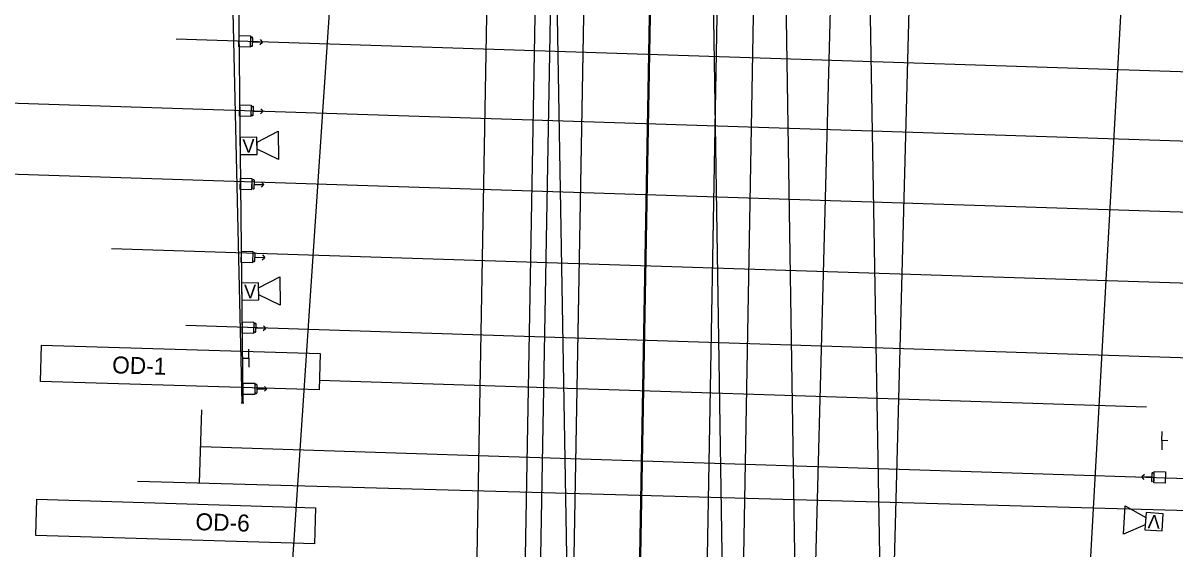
# Model space of a CAD drawing. Extents: x 925524 to 926006, y 853415 to 857998.
# Drawn here: x 925686 to 925876.1, y 853545.3 to 853632 of the extents above; entities that cross this region are included whole.
import ezdxf

# ---------------------------------------------------------------- set-up
doc = ezdxf.new("R2010")
doc.units = 0
for name, color, linetype in [('ConduitDB', 7, 'Continuous'), ('ConstLines', 7, 'Continuous'), ('DetectorVeh', 7, 'Continuous'), ('NonPlottingEle_dp', 7, 'Continuous'), ('OverheadStr', 7, 'Continuous'), ('ScratchEle2_dp', 7, 'Continuous'), ('SignalHead', 7, 'Continuous'), ('SignPanel', 7, 'Continuous'), ('TextMinor', 7, 'Continuous')]:
    doc.layers.add(name, color=color, linetype=linetype)

msp = doc.modelspace()

# ---------------------------------------------------------------- linework, layer by layer
at = {"layer": 'ConduitDB'}
for p, q in [((925869.15, 853671.01), (925859.35, 853493.47)), ((925738.35, 853660.55), (925727.58, 853500.34))]:
    msp.add_line(p, q, dxfattribs=at)
at = {"layer": 'ConstLines'}
for p, q in [((925821.17, 853708.61), (925814.44, 853457.33)), ((925834.16, 853708.27), (925827.43, 853456.98)), ((925807.55, 853693.24), (925803.33, 853457.33)), ((925773.58, 853666.98), (925777.16, 853456.64))]:
    msp.add_line(p, q, dxfattribs=at)
at = {"layer": 'DetectorVeh'}
for p, q in [((925724.65, 853611.19), (925724.63, 853612.36)), ((925724.92, 853587.18), (925724.9, 853588.35)), ((925871.23, 853550.43), (925871.16, 853549.26))]:
    msp.add_line(p, q, dxfattribs=at)
for points in [[(925724.62, 853613.18), (925721.81, 853613.13), (925721.85, 853610.32), (925724.67, 853610.36)], [(925724.89, 853589.17), (925722.07, 853589.13), (925722.12, 853586.32), (925724.93, 853586.36)], [(925871.11, 853548.44), (925873.92, 853548.27), (925874.09, 853551.08), (925871.28, 853551.25)]]:
    msp.add_lwpolyline(points, close=True, dxfattribs=at)
for points in [[(925724.63, 853612.36), (925728.12, 853614.17), (925728.2, 853609.49), (925724.65, 853611.19)], [(925724.9, 853588.35), (925728.38, 853590.17), (925728.46, 853585.49), (925724.92, 853587.18)], [(925871.16, 853549.26), (925867.55, 853547.71), (925867.83, 853552.39), (925871.23, 853550.43)]]:
    msp.add_lwpolyline(points, dxfattribs=at)
at = {"layer": 'NonPlottingEle_dp'}
for p, q in [((925763.22, 853675.01), (925759.78, 853483.16)), ((925779.22, 853674.95), (925775.92, 853490.92)), ((925790.22, 853674.76), (925786.81, 853484.28)), ((925801.22, 853674.56), (925797.82, 853484.67)), ((925897.69, 853623.31), (925711.32, 853629.35)), ((926004.06, 853608.44), (925681.22, 853618.9)), ((926002.97, 853596.74), (925680.13, 853607.2)), ((926006.46, 853584.89), (925700.62, 853594.79)), ((925905.88, 853575.86), (925712.86, 853582.11)), ((925871.38, 853568.63), (925734.93, 853573.05)), ((925715.14, 853556.15), (925715.53, 853568.2)), ((925715.34, 853562.18), (925878.03, 853556.91)), ((925704.91, 853556.44), (925916.29, 853550.54))]:
    msp.add_line(p, q, dxfattribs=at)
at = {"layer": 'OverheadStr'}
for p, q in [((925720.35, 853647.29), (925722.13, 853569.31)), ((925721.43, 853647.31), (925722.3, 853569.31)), ((925722.43, 853569.31), (925722, 853569.31))]:
    msp.add_line(p, q, dxfattribs=at)
at = {"layer": 'ScratchEle2_dp'}
for p, q in [((925798.69, 853711.44), (925803.07, 853432.2)), ((925829.04, 853446.57), (925824.52, 853709.82)), ((925815.37, 853415.34), (925810.9, 853700.12)), ((925763.52, 853691.77), (925759.97, 853493.66)), ((925771.52, 853691.62), (925767.97, 853493.51)), ((925779.52, 853691.48), (925775.97, 853493.37)), ((925773.97, 853688.76), (925770.55, 853498.1)), ((925790.32, 853688.01), (925786.74, 853488.27)), ((925801.46, 853687.88), (925797.66, 853476.1))]:
    msp.add_line(p, q, dxfattribs=at)
at = {"layer": 'SignalHead'}
for p, q in [((925723.88, 853628.33), (925723.92, 853629.55)), ((925723.9, 853628.94), (925725.51, 853628.89)), ((925725.1, 853628.5), (925725.51, 853628.89)), ((925725.13, 853629.3), (925725.51, 853628.89)), ((925724.01, 853616.9), (925724.05, 853618.13)), ((925724.03, 853617.51), (925725.64, 853617.46)), ((925725.23, 853617.07), (925725.64, 853617.46)), ((925725.25, 853617.87), (925725.64, 853617.46)), ((925724.15, 853604.79), (925724.19, 853606.02)), ((925724.17, 853605.41), (925725.77, 853605.36)), ((925725.36, 853604.97), (925725.77, 853605.36)), ((925725.39, 853605.77), (925725.77, 853605.36)), ((925724.28, 853592.78), (925724.32, 853594.01)), ((925724.3, 853593.4), (925725.91, 853593.35)), ((925725.5, 853592.96), (925725.91, 853593.35)), ((925725.52, 853593.76), (925725.91, 853593.35)), ((925724.45, 853581.11), (925724.49, 853582.34)), ((925725.69, 853582.09), (925726.08, 853581.67)), ((925724.47, 853581.73), (925726.08, 853581.67)), ((925725.67, 853581.29), (925726.08, 853581.67)), ((925724.64, 853571.05), (925724.64, 853572.28)), ((925724.64, 853571.67), (925726.25, 853571.67)), ((925725.85, 853572.07), (925726.25, 853571.67)), ((925725.85, 853571.27), (925726.25, 853571.67)), ((925871.03, 853557.54), (925870.62, 853557.15)), ((925872.24, 853557.71), (925872.2, 853556.48)), ((925872.22, 853557.1), (925870.62, 853557.15)), ((925871, 853556.74), (925870.62, 853557.15))]:
    msp.add_line(p, q, dxfattribs=at)
for points in [[(925723.54, 853629.89), (925723.48, 853628.02), (925721.61, 853628.08), (925721.67, 853629.95)], [(925723.67, 853618.46), (925723.61, 853616.59), (925721.73, 853616.65), (925721.79, 853618.52)], [(925723.8, 853606.36), (925723.74, 853604.48), (925721.87, 853604.55), (925721.93, 853606.42)], [(925723.94, 853594.35), (925723.88, 853592.47), (925722, 853592.53), (925722.06, 853594.41)], [(925724.11, 853582.68), (925724.04, 853580.8), (925722.17, 853580.86), (925722.23, 853582.74)], [(925724.25, 853572.61), (925724.25, 853570.73), (925722.37, 853570.73), (925722.37, 853572.61)], [(925872.59, 853556.15), (925872.65, 853558.02), (925874.52, 853557.96), (925874.46, 853556.09)]]:
    msp.add_lwpolyline(points, close=True, dxfattribs=at)
for points in [[(925723.53, 853629.57), (925723.49, 853628.34)], [(925723.66, 853618.14), (925723.62, 853616.91)], [(925723.79, 853606.04), (925723.75, 853604.81)], [(925723.93, 853594.02), (925723.89, 853592.8)], [(925724.09, 853582.35), (925724.05, 853581.13)], [(925724.25, 853572.28), (925724.25, 853571.06)], [(925872.6, 853556.47), (925872.64, 853557.7)]]:
    msp.add_lwpolyline(points, dxfattribs=at)
for centre, radius, start, end in [((925722.71, 853631.66), 2.25, 291.3617, 297.4649), ((925723.8, 853629.56), 0.121, 358.1451, 117.4649), ((925722.54, 853626.3), 2.25, 58.8253, 64.9285), ((925723.76, 853628.33), 0.121, 238.8253, 358.1451), ((925722.84, 853620.23), 2.25, 291.3617, 297.4649), ((925723.93, 853618.13), 0.121, 358.1451, 117.4649), ((925722.67, 853614.87), 2.25, 58.8253, 64.9285), ((925723.89, 853616.9), 0.121, 238.8253, 358.1451), ((925722.8, 853602.77), 2.25, 58.8253, 64.9285), ((925722.97, 853608.13), 2.25, 291.3617, 297.4649), ((925724.03, 853604.8), 0.121, 238.8253, 358.1451), ((925724.07, 853606.03), 0.121, 358.1451, 117.4649), ((925723.11, 853596.12), 2.25, 291.3617, 297.4649), ((925724.2, 853594.02), 0.121, 358.1451, 117.4649), ((925722.93, 853590.76), 2.25, 58.8253, 64.9285), ((925724.16, 853592.79), 0.121, 238.8253, 358.1451), ((925723.28, 853584.45), 2.25, 291.3617, 297.4649), ((925724.37, 853582.35), 0.121, 358.1451, 117.4649), ((925723.1, 853579.09), 2.25, 58.8253, 64.9285), ((925724.33, 853581.12), 0.121, 238.8253, 358.1451), ((925723.36, 853574.35), 2.25, 293.2166, 299.3198), ((925723.36, 853568.99), 2.25, 60.6802, 66.7834), ((925724.52, 853572.28), 0.121, 0, 119.3198), ((925724.52, 853571.05), 0.121, 240.6802, 360), ((925872.36, 853557.71), 0.121, 58.8253, 178.1451), ((925873.59, 853559.74), 2.25, 238.8253, 244.9285), ((925872.32, 853556.48), 0.121, 178.1451, 297.4649), ((925873.42, 853554.38), 2.25, 111.3617, 117.4649)]:
    msp.add_arc(centre, radius, start, end, dxfattribs=at)
at = {"layer": 'SignPanel'}
for p, q in [((925723.26, 853576.73), (925723.26, 853578.23)), ((925722.26, 853576.73), (925723.26, 853576.73)), ((925723.26, 853576.73), (925723.26, 853575.23)), ((925873.9, 853563.13), (925873.87, 853561.63)), ((925873.9, 853563.13), (925873.92, 853564.63)), ((925874.89, 853563.12), (925873.9, 853563.13))]:
    msp.add_line(p, q, dxfattribs=at)
at = {"layer": 'TextMinor'}
for points in [[(925735.06, 853577.5), (925734.88, 853571.5), (925688.9, 853572.91), (925689.08, 853578.9), (925735.06, 853577.5)], [(925734.29, 853552.07), (925734.1, 853546.08), (925688.13, 853547.48), (925688.31, 853553.47), (925734.29, 853552.07)]]:
    msp.add_lwpolyline(points, dxfattribs=at)

# ---------------------------------------------------------------- texts
at = {"layer": 'DetectorVeh'}
for rotation, p in [(0.9742, (925722.25, 853610.61)), (0.9742, (925722.52, 853586.6)), (176.5443, (925873.67, 853550.82))]:
    msp.add_text('V', height=2.25, rotation=rotation, dxfattribs=at).set_placement(p)
at = {"layer": 'TextMinor'}
for s, p in [('OD-1', (925700.7, 853574.25)), ('OD-6', (925714.45, 853548.38))]:
    msp.add_text(s, height=2.8, rotation=358.2527, dxfattribs=at).set_placement(p)

doc.saveas('drawing.dxf')
